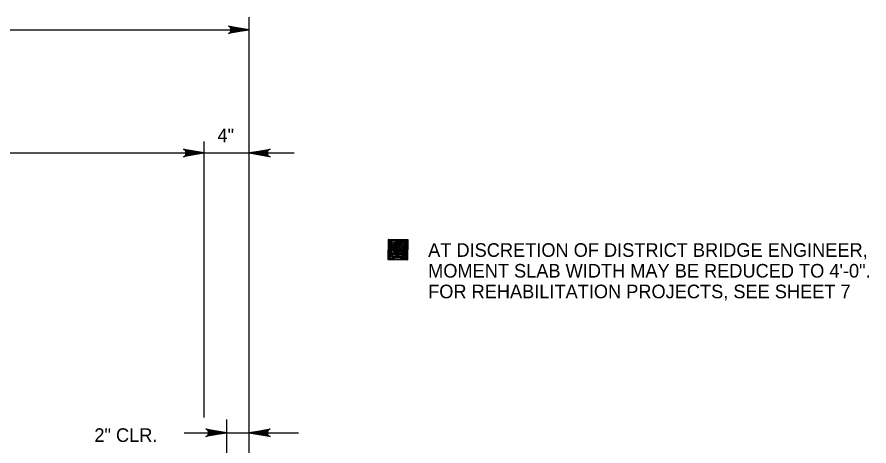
# Model space of a CAD drawing. Extents: x 638167 to 640248, y 296544 to 298920.
# Drawn here: x 638526.2 to 638718.6, y 296748.5 to 296845.3 of the extents above; entities that cross this region are included whole.
import ezdxf

# ---------------------------------------------------------------- set-up
doc = ezdxf.new("R2010")
doc.units = 0
doc.layers.add('1', color=7, linetype='Continuous')

msp = doc.modelspace()

# ---------------------------------------------------------------- linework, layer by layer
at = {"layer": '1'}
for p, q in [((638578.63, 296692.57), (638578.63, 296845.26)), ((638283.35, 296842.39), (638578.63, 296842.39)), ((638568.47, 296754.85), (638568.47, 296817.2)), ((638283.35, 296814.58), (638588.76, 296814.58)), ((638612.22, 296792.76), (638612.22, 296792.76)), ((638573.55, 296685.73), (638573.55, 296754.42)), ((638563.92, 296751.44), (638589.75, 296751.44))]:
    msp.add_line(p, q, dxfattribs=at)
for points in [[(638578.63, 296842.39), (638573.93, 296841.51), (638574.11, 296841.63), (638574.29, 296841.76), (638574.39, 296841.92), (638574.48, 296842.07), (638574.51, 296842.23), (638574.53, 296842.39), (638574.51, 296842.55), (638574.48, 296842.7), (638574.39, 296842.86), (638574.29, 296843.02), (638574.11, 296843.14), (638573.93, 296843.27), (638578.63, 296842.39), (638574.11, 296843.14), (638574.29, 296843.02), (638578.63, 296842.39), (638574.39, 296842.86), (638574.48, 296842.7), (638578.63, 296842.39), (638574.51, 296842.55), (638574.53, 296842.39), (638578.63, 296842.39), (638574.51, 296842.23), (638574.48, 296842.07), (638578.63, 296842.39), (638574.39, 296841.92), (638574.29, 296841.76), (638578.63, 296842.39), (638574.11, 296841.63)], [(638568.47, 296814.58), (638563.77, 296813.7), (638563.95, 296813.82), (638564.13, 296813.95), (638564.23, 296814.11), (638564.32, 296814.26), (638564.35, 296814.42), (638564.37, 296814.58), (638564.35, 296814.74), (638564.32, 296814.89), (638564.23, 296815.05), (638564.13, 296815.21), (638563.95, 296815.33), (638563.77, 296815.46), (638568.47, 296814.58), (638563.95, 296815.33), (638564.13, 296815.21), (638568.47, 296814.58), (638564.23, 296815.05), (638564.32, 296814.89), (638568.47, 296814.58), (638564.35, 296814.74), (638564.37, 296814.58), (638568.47, 296814.58), (638564.35, 296814.42), (638564.32, 296814.26), (638568.47, 296814.58), (638564.23, 296814.11), (638564.13, 296813.95), (638568.47, 296814.58), (638563.95, 296813.82)], [(638578.63, 296814.58), (638583.33, 296815.46), (638583.14, 296815.33), (638582.96, 296815.21), (638582.87, 296815.05), (638582.78, 296814.89), (638582.75, 296814.74), (638582.72, 296814.58), (638582.75, 296814.42), (638582.78, 296814.26), (638582.87, 296814.11), (638582.96, 296813.95), (638583.14, 296813.82), (638583.33, 296813.7), (638578.63, 296814.58), (638583.14, 296813.82), (638582.96, 296813.95), (638578.63, 296814.58), (638582.87, 296814.11), (638582.78, 296814.26), (638578.63, 296814.58), (638582.75, 296814.42), (638582.72, 296814.58), (638578.63, 296814.58), (638582.75, 296814.74), (638582.78, 296814.89), (638578.63, 296814.58), (638582.87, 296815.05), (638582.96, 296815.21), (638578.63, 296814.58), (638583.14, 296815.33)], [(638609.98, 296795.05), (638609.93, 296790.53), (638614.46, 296790.48), (638614.51, 296795), (638609.98, 296795.05), (638610.24, 296790.81), (638614.18, 296790.65), (638614.29, 296794.78), (638610.31, 296794.73), (638610.49, 296791.12), (638613.94, 296790.96), (638614.04, 296794.41), (638610.55, 296794.42), (638610.77, 296791.39), (638613.73, 296791.3), (638613.73, 296794.17), (638610.89, 296794.01), (638611.11, 296791.67), (638613.39, 296791.58), (638613.41, 296793.86), (638611.19, 296793.7), (638611.42, 296792.04), (638613.05, 296791.86), (638613.16, 296793.5), (638611.44, 296793.58), (638611.58, 296792.31), (638612.81, 296792.24), (638612.82, 296793.1), (638611.96, 296793.29), (638611.89, 296792.55), (638612.5, 296792.49), (638612.57, 296792.86), (638612.26, 296792.86), (638610.19, 296794.92), (638614.38, 296794.81), (638610.08, 296790.6), (638614.12, 296790.83), (638610.25, 296794.73), (638614.02, 296793.36), (638610.36, 296794.05), (638613.92, 296792.04), (638610.32, 296792.97), (638613.82, 296791.39), (638610.5, 296791.98), (638613.57, 296790.96), (638610.95, 296790.96), (638611.73, 296794.65), (638612.24, 296791.01), (638612.71, 296794.58), (638613.91, 296790.87), (638614.22, 296794.59), (638612.86, 296791.56), (638610.13, 296794.79), (638610.42, 296790.87), (638611.04, 296794.04), (638613.98, 296794.54), (638610.68, 296794.79)], [(638573.55, 296751.44), (638568.85, 296750.56), (638569.03, 296750.69), (638569.21, 296750.81), (638569.31, 296750.97), (638569.4, 296751.13), (638569.43, 296751.28), (638569.45, 296751.44), (638569.43, 296751.6), (638569.4, 296751.76), (638569.31, 296751.91), (638569.21, 296752.07), (638569.03, 296752.2), (638568.85, 296752.32), (638573.55, 296751.44), (638569.03, 296752.2), (638569.21, 296752.07), (638573.55, 296751.44), (638569.31, 296751.91), (638569.4, 296751.76), (638573.55, 296751.44), (638569.43, 296751.6), (638569.45, 296751.44), (638573.55, 296751.44), (638569.43, 296751.28), (638569.4, 296751.13), (638573.55, 296751.44), (638569.31, 296750.97), (638569.21, 296750.81), (638573.55, 296751.44), (638569.03, 296750.69)], [(638578.63, 296751.44), (638583.33, 296752.32), (638583.14, 296752.2), (638582.96, 296752.07), (638582.87, 296751.91), (638582.78, 296751.76), (638582.75, 296751.6), (638582.72, 296751.44), (638582.75, 296751.28), (638582.78, 296751.13), (638582.87, 296750.97), (638582.96, 296750.81), (638583.14, 296750.69), (638583.33, 296750.56), (638578.63, 296751.44), (638583.14, 296750.69), (638582.96, 296750.81), (638578.63, 296751.44), (638582.87, 296750.97), (638582.78, 296751.13), (638578.63, 296751.44), (638582.75, 296751.28), (638582.72, 296751.44), (638578.63, 296751.44), (638582.75, 296751.6), (638582.78, 296751.76), (638578.63, 296751.44), (638582.87, 296751.91), (638582.96, 296752.07), (638578.63, 296751.44), (638583.14, 296752.2)]]:
    msp.add_lwpolyline(points, dxfattribs=at)

# ---------------------------------------------------------------- texts
for s, p in [('4"', (638571.46, 296817.02)), ('AT DISCRETION OF DISTRICT BRIDGE ENGINEER, ', (638619.04, 296791.14)), ('MOMENT SLAB WIDTH MAY BE REDUCED TO 4\'-0". ', (638619.04, 296786.46)), ('FOR REHABILITATION PROJECTS, SEE SHEET 7', (638619.04, 296781.79)), ('2" CLR.', (638543.66, 296749.37))]:
    msp.add_text(s, height=3.072, dxfattribs=at).set_placement(p)

doc.saveas('drawing.dxf')
